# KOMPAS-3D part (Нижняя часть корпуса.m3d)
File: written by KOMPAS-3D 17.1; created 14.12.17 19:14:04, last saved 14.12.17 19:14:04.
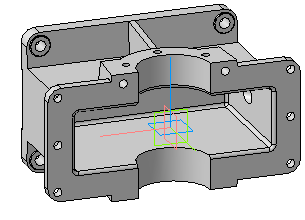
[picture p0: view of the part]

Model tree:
1. Операция без истории:1

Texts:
  Нижняя часть корпуса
